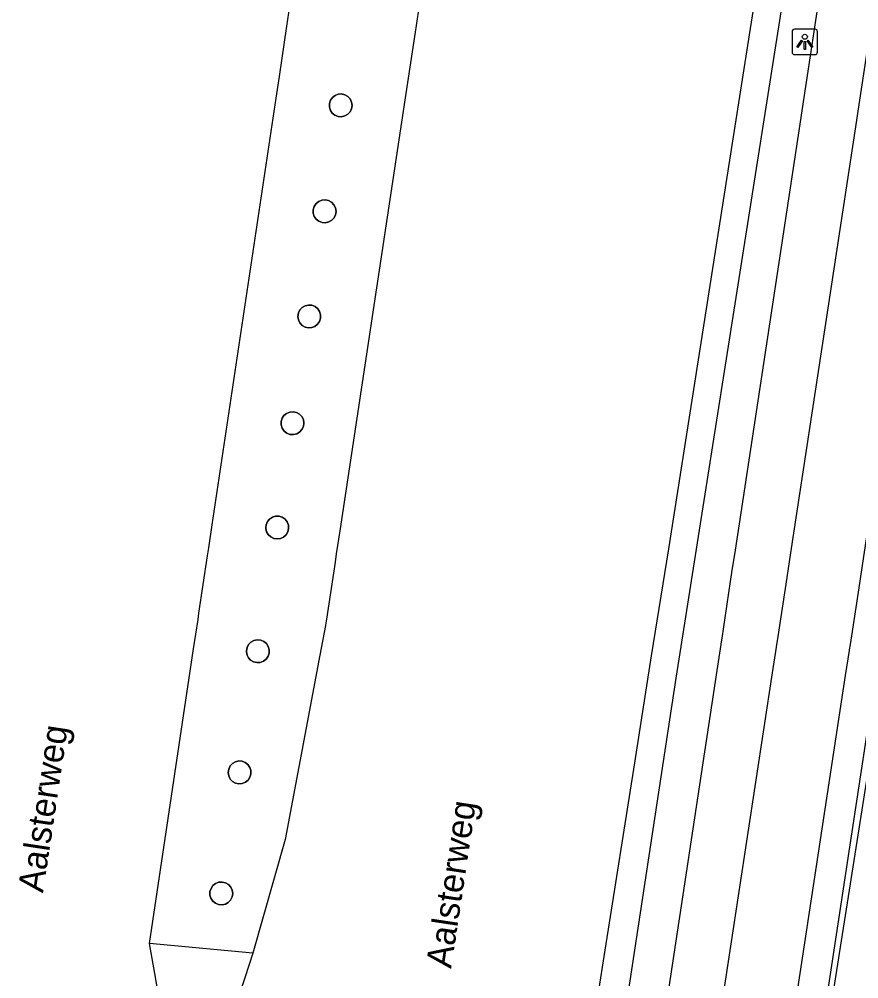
# Model space of a CAD drawing. Extents: x 161486 to 162249, y 379484 to 380829.
# Drawn here: x 161490.61 to 161523.59, y 379544.29 to 379582.01 of the extents above; entities that cross this region are included whole.
import ezdxf

# ---------------------------------------------------------------- set-up
doc = ezdxf.new("R2010")
doc.units = 0
for name, color, linetype in [('IMGEO_Berm_groen', 7, 'Continuous'), ('IMGEO_Berm_onverhard', 7, 'Continuous'), ('IMGEO_Fietspad_open', 7, 'Continuous'), ('IMGEO_Lichtpunt', 7, 'Continuous'), ('IMGEO_Openbare_ruimte_label', 7, 'Continuous'), ('IMGEO_Pijler', 7, 'Continuous'), ('IMGEO_Rijbaan_regionaal_gesloten', 7, 'Continuous'), ('IMGEO_Terreindeel_gesloten', 7, 'Continuous'), ('IMGEO_Verkeerseiland_open', 7, 'Continuous'), ('IMGEO_Voetpad_open', 7, 'Continuous')]:
    doc.layers.add(name, color=color, linetype=linetype)

msp = doc.modelspace()

# ---------------------------------------------------------------- linework, layer by layer
at = {"layer": 'IMGEO_Berm_groen'}
for points in [[(161516.417, 379556.106), (161526.18, 379618.14)], [(161527.294, 379617.58), (161527.259, 379617.352), (161527.039, 379615.902), (161525.083, 379603.014), (161524.95, 379602.133), (161524.942, 379602.083), (161524.556, 379599.541), (161524.518, 379599.289), (161524.48, 379599.039), (161524.465, 379598.94), (161524.312, 379597.933), (161521.822, 379581.524), (161521.704, 379580.745), (161521.403, 379578.761), (161521.27, 379577.888), (161518.729, 379561.143), (161518.595, 379560.258), (161518.543, 379559.914), (161518.204, 379557.678), (161518.171, 379557.462), (161518.167, 379557.439), (161518.011, 379556.409), (161516.057, 379543.535)], [(161514.521, 379543.608), (161516.417, 379556.106)]]:
    msp.add_lwpolyline(points, dxfattribs=at)
at = {"layer": 'IMGEO_Berm_onverhard'}
for points in [[(161503.402, 379579.044), (161503.517, 379578.976), (161503.608, 379578.878), (161503.665, 379578.757), (161503.685, 379578.624), (161503.665, 379578.492), (161503.606, 379578.372), (161503.515, 379578.274), (161503.399, 379578.207), (161503.269, 379578.177), (161503.135, 379578.187), (161503.011, 379578.236), (161502.906, 379578.319), (161502.83, 379578.429), (161502.79, 379578.557), (161502.79, 379578.691), (161502.819, 379578.798), (161502.832, 379578.825), (161502.908, 379578.935), (161503.013, 379579.018), (161503.138, 379579.065), (161503.272, 379579.074), (161503.402, 379579.044)], [(161502.877, 379574.815), (161502.97, 379574.718), (161503.029, 379574.598), (161503.052, 379574.459), (161503.032, 379574.327), (161502.974, 379574.206), (161502.883, 379574.108), (161502.767, 379574.041), (161502.637, 379574.01), (161502.504, 379574.02), (161502.379, 379574.068), (161502.274, 379574.151), (161502.198, 379574.261), (161502.157, 379574.388), (161502.156, 379574.522), (161502.194, 379574.65), (161502.269, 379574.762), (161502.372, 379574.846), (161502.496, 379574.897), (161502.63, 379574.908), (161502.76, 379574.88), (161502.877, 379574.815)], [(161502.231, 379570.716), (161502.335, 379570.631), (161502.409, 379570.52), (161502.448, 379570.392), (161502.446, 379570.258), (161502.406, 379570.13), (161502.33, 379570.02), (161502.225, 379569.937), (161502.1, 379569.889), (161501.967, 379569.88), (161501.836, 379569.91), (161501.721, 379569.977), (161501.63, 379570.075), (161501.572, 379570.196), (161501.552, 379570.328), (161501.574, 379570.468), (161501.634, 379570.587), (161501.726, 379570.684), (161501.843, 379570.749), (161501.974, 379570.777), (161502.107, 379570.766), (161502.231, 379570.716)], [(161501.709, 379566.392), (161501.769, 379566.273), (161501.791, 379566.133), (161501.771, 379566.001), (161501.713, 379565.88), (161501.622, 379565.782), (161501.507, 379565.715), (161501.376, 379565.685), (161501.243, 379565.694), (161501.118, 379565.742), (161501.013, 379565.825), (161500.937, 379565.935), (161500.897, 379566.063), (161500.895, 379566.196), (161500.934, 379566.325), (161501.008, 379566.436), (161501.112, 379566.52), (161501.236, 379566.571), (161501.369, 379566.582), (161501.5, 379566.554), (161501.617, 379566.489), (161501.709, 379566.392)], [(161501.05, 379562.359), (161501.132, 379562.254), (161501.18, 379562.129), (161501.189, 379561.995), (161501.158, 379561.865), (161501.091, 379561.749), (161500.992, 379561.659), (161500.871, 379561.602), (161500.739, 379561.582), (161500.607, 379561.603), (161500.486, 379561.661), (161500.388, 379561.752), (161500.322, 379561.868), (161500.292, 379561.998), (161500.291, 379562.039), (161500.303, 379562.139), (161500.354, 379562.263), (161500.439, 379562.366), (161500.551, 379562.44), (161500.679, 379562.478), (161500.813, 379562.476), (161500.94, 379562.435), (161501.05, 379562.359)], [(161500.392, 379557.359), (161500.429, 379557.23), (161500.427, 379557.096), (161500.385, 379556.969), (161500.307, 379556.86), (161500.201, 379556.779), (161500.076, 379556.732), (161499.942, 379556.724), (161499.812, 379556.756), (161499.697, 379556.824), (161499.619, 379556.912), (161499.563, 379557.01), (161499.534, 379557.141), (161499.533, 379557.185), (161499.557, 379557.317), (161499.618, 379557.436), (161499.712, 379557.531), (161499.829, 379557.595), (161499.96, 379557.622), (161500.093, 379557.608), (161500.217, 379557.557), (161500.32, 379557.471), (161500.392, 379557.359)], [(161499.709, 379552.477), (161499.71, 379552.343), (161499.672, 379552.215), (161499.598, 379552.103), (161499.494, 379552.019), (161499.37, 379551.968), (161499.237, 379551.957), (161499.106, 379551.985), (161498.989, 379552.05), (161498.897, 379552.147), (161498.837, 379552.267), (161498.815, 379552.406), (161498.835, 379552.538), (161498.893, 379552.659), (161498.983, 379552.757), (161499.099, 379552.824), (161499.229, 379552.855), (161499.363, 379552.845), (161499.488, 379552.797), (161499.593, 379552.714), (161499.669, 379552.604), (161499.709, 379552.477)], [(161498.995, 379547.649), (161498.973, 379547.51), (161498.913, 379547.39), (161498.821, 379547.294), (161498.704, 379547.228), (161498.573, 379547.2), (161498.44, 379547.212), (161498.316, 379547.262), (161498.212, 379547.347), (161498.138, 379547.458), (161498.1, 379547.586), (161498.101, 379547.72), (161498.141, 379547.847), (161498.217, 379547.957), (161498.322, 379548.04), (161498.447, 379548.088), (161498.581, 379548.098), (161498.711, 379548.068), (161498.827, 379548), (161498.917, 379547.902), (161498.975, 379547.782), (161498.995, 379547.649)]]:
    msp.add_lwpolyline(points, dxfattribs=at)
at = {"layer": 'IMGEO_Fietspad_open'}
for points in [[(161529.477, 379617.475), (161529.443, 379617.251), (161529.222, 379615.794), (161527.27, 379602.91), (161527.136, 379602.026), (161527.129, 379601.975), (161526.744, 379599.436), (161526.705, 379599.18), (161526.668, 379598.93), (161526.652, 379598.831), (161526.5, 379597.828), (161524.015, 379581.417), (161523.897, 379580.639), (161523.596, 379578.655), (161523.463, 379577.78), (161520.907, 379561.037), (161520.772, 379560.153), (161520.72, 379559.808), (161520.379, 379557.573), (161520.346, 379557.359), (161520.342, 379557.335), (161520.188, 379556.324), (161518.221, 379543.432)], [(161521.107, 379543.294), (161523.074, 379556.211), (161523.224, 379557.197), (161523.228, 379557.223), (161523.26, 379557.434), (161523.6, 379559.667), (161523.653, 379560.015), (161523.788, 379560.897), (161526.337, 379577.638), (161526.471, 379578.515), (161526.773, 379580.5), (161526.891, 379581.277), (161529.388, 379597.69), (161529.539, 379598.688), (161529.554, 379598.787), (161529.588, 379599.006), (161529.593, 379599.038), (161529.632, 379599.297), (161530.018, 379601.833), (161530.026, 379601.884), (161530.161, 379602.772), (161532.12, 379615.65), (161532.343, 379617.118), (161532.376, 379617.336)]]:
    msp.add_lwpolyline(points, dxfattribs=at)
at = {"layer": 'IMGEO_Lichtpunt'}
for p, q in [((161520.971, 379581.522), (161520.971, 379580.715)), ((161520.971, 379581.522), (161520.971, 379580.715)), ((161521.873, 379581.617), (161521.065, 379581.617)), ((161521.873, 379581.617), (161521.065, 379581.617)), ((161521.967, 379580.715), (161521.967, 379581.522)), ((161521.967, 379580.715), (161521.967, 379581.522)), ((161521.065, 379580.621), (161521.873, 379580.621)), ((161521.065, 379580.621), (161521.873, 379580.621))]:
    msp.add_line(p, q, dxfattribs=at)
for points in [[(161521.345, 379581.186), (161521.384, 379581.158), (161521.196, 379580.896), (161521.158, 379580.923), (161521.345, 379581.186)], [(161521.447, 379581.138), (161521.494, 379581.138), (161521.494, 379580.816), (161521.447, 379580.816), (161521.447, 379581.138)], [(161521.557, 379581.158), (161521.595, 379581.185), (161521.782, 379580.923), (161521.743, 379580.895), (161521.557, 379581.158)]]:
    msp.add_lwpolyline(points, dxfattribs=at)
msp.add_circle((161521.47, 379581.32), 0.0994, dxfattribs=at)
for centre, start, end in [((161521.065, 379581.522), 90, 180), ((161521.065, 379581.522), 90, 180), ((161521.873, 379581.522), 0, 90), ((161521.873, 379581.522), 0, 90), ((161521.065, 379580.715), 180, 270), ((161521.065, 379580.715), 180, 270), ((161521.873, 379580.715), 270, 0), ((161521.873, 379580.715), 270, 360)]:
    msp.add_arc(centre, 0.0946, start, end, dxfattribs=at)
at = {"layer": 'IMGEO_Pijler'}
for points in [[(161503.685, 379578.624), (161503.665, 379578.757), (161503.608, 379578.878), (161503.517, 379578.976), (161503.402, 379579.044), (161503.272, 379579.074), (161503.138, 379579.065), (161503.013, 379579.018), (161502.908, 379578.935), (161502.832, 379578.825), (161502.819, 379578.798), (161502.79, 379578.691), (161502.79, 379578.557), (161502.83, 379578.429), (161502.906, 379578.319), (161503.011, 379578.236), (161503.135, 379578.187), (161503.269, 379578.177), (161503.399, 379578.207), (161503.515, 379578.274), (161503.606, 379578.372), (161503.665, 379578.492)], [(161502.97, 379574.718), (161502.877, 379574.815), (161502.76, 379574.88), (161502.63, 379574.908), (161502.496, 379574.897), (161502.372, 379574.846), (161502.269, 379574.762), (161502.194, 379574.65), (161502.156, 379574.522), (161502.157, 379574.388), (161502.198, 379574.261), (161502.274, 379574.151), (161502.379, 379574.068), (161502.504, 379574.02), (161502.637, 379574.01), (161502.767, 379574.041), (161502.883, 379574.108), (161502.974, 379574.206), (161503.032, 379574.327), (161503.052, 379574.459), (161503.029, 379574.598)], [(161502.448, 379570.392), (161502.409, 379570.52), (161502.335, 379570.631), (161502.231, 379570.716), (161502.107, 379570.766), (161501.974, 379570.777), (161501.843, 379570.749), (161501.726, 379570.684), (161501.634, 379570.587), (161501.574, 379570.468), (161501.552, 379570.328), (161501.572, 379570.196), (161501.63, 379570.075), (161501.721, 379569.977), (161501.836, 379569.91), (161501.967, 379569.88), (161502.1, 379569.889), (161502.225, 379569.937), (161502.33, 379570.02), (161502.406, 379570.13), (161502.446, 379570.258)], [(161501.769, 379566.273), (161501.709, 379566.392), (161501.617, 379566.489), (161501.5, 379566.554), (161501.369, 379566.582), (161501.236, 379566.571), (161501.112, 379566.52), (161501.008, 379566.436), (161500.934, 379566.325), (161500.895, 379566.196), (161500.897, 379566.063), (161500.937, 379565.935), (161501.013, 379565.825), (161501.118, 379565.742), (161501.243, 379565.694), (161501.376, 379565.685), (161501.507, 379565.715), (161501.622, 379565.782), (161501.713, 379565.88), (161501.771, 379566.001), (161501.791, 379566.133)], [(161501.18, 379562.129), (161501.132, 379562.254), (161501.05, 379562.359), (161500.94, 379562.435), (161500.813, 379562.476), (161500.679, 379562.478), (161500.551, 379562.44), (161500.439, 379562.366), (161500.354, 379562.263), (161500.303, 379562.139), (161500.291, 379562.039), (161500.292, 379561.998), (161500.322, 379561.868), (161500.388, 379561.752), (161500.486, 379561.661), (161500.607, 379561.603), (161500.739, 379561.582), (161500.871, 379561.602), (161500.992, 379561.659), (161501.091, 379561.749), (161501.158, 379561.865), (161501.189, 379561.995)], [(161500.429, 379557.23), (161500.392, 379557.359), (161500.32, 379557.471), (161500.217, 379557.557), (161500.093, 379557.608), (161499.96, 379557.622), (161499.829, 379557.595), (161499.712, 379557.531), (161499.618, 379557.436), (161499.557, 379557.317), (161499.533, 379557.185), (161499.534, 379557.141), (161499.563, 379557.01), (161499.619, 379556.912), (161499.697, 379556.824), (161499.812, 379556.756), (161499.942, 379556.724), (161500.076, 379556.732), (161500.201, 379556.779), (161500.307, 379556.86), (161500.385, 379556.969), (161500.427, 379557.096)], [(161499.709, 379552.477), (161499.669, 379552.604), (161499.593, 379552.714), (161499.488, 379552.797), (161499.363, 379552.845), (161499.229, 379552.855), (161499.099, 379552.824), (161498.983, 379552.757), (161498.893, 379552.659), (161498.835, 379552.538), (161498.815, 379552.406), (161498.837, 379552.267), (161498.897, 379552.147), (161498.989, 379552.05), (161499.106, 379551.985), (161499.237, 379551.957), (161499.37, 379551.968), (161499.494, 379552.019), (161499.598, 379552.103), (161499.672, 379552.215), (161499.71, 379552.343)], [(161498.975, 379547.782), (161498.917, 379547.902), (161498.827, 379548), (161498.711, 379548.068), (161498.581, 379548.098), (161498.447, 379548.088), (161498.322, 379548.04), (161498.217, 379547.957), (161498.141, 379547.847), (161498.101, 379547.72), (161498.1, 379547.586), (161498.138, 379547.458), (161498.212, 379547.347), (161498.316, 379547.262), (161498.44, 379547.212), (161498.573, 379547.2), (161498.704, 379547.228), (161498.821, 379547.294), (161498.913, 379547.39), (161498.973, 379547.51), (161498.995, 379547.649)]]:
    msp.add_lwpolyline(points, close=True, dxfattribs=at)
at = {"layer": 'IMGEO_Rijbaan_regionaal_gesloten'}
for points in [[(161513.354, 379543.664), (161513.63, 379545.417), (161514.79, 379552.78), (161515.453, 379556.988), (161516.133, 379561.19), (161519.339, 379581.651), (161522.723, 379603.127), (161524.864, 379616.082), (161525.01, 379617.635), (161525.102, 379618.199)], [(161495.724, 379545.685), (161497.459, 379557.264), (161497.632, 379558.421), (161497.669, 379558.667), (161498.006, 379560.919), (161498.053, 379561.232), (161498.19, 379562.141), (161500.701, 379578.903), (161500.83, 379579.763), (161501.126, 379581.741), (161501.244, 379582.528), (161503.7, 379598.919), (161503.856, 379599.964), (161503.871, 379600.063), (161503.901, 379600.263), (161503.908, 379600.307), (161503.942, 379600.535), (161504.326, 379603.098), (161504.333, 379603.144), (161504.461, 379603.999), (161506.336, 379616.511)], [(161511.348, 379615.831), (161509.524, 379603.758), (161509.394, 379602.896), (161509.387, 379602.85), (161509, 379600.291), (161508.965, 379600.057), (161508.959, 379600.016), (161508.928, 379599.812), (161508.913, 379599.713), (161508.756, 379598.677), (161506.279, 379582.283), (161506.161, 379581.497), (161505.862, 379579.518), (161505.731, 379578.655), (161503.2, 379561.897), (161503.064, 379561.002), (161503.015, 379560.674), (161502.675, 379558.426), (161502.641, 379558.199), (161502.638, 379558.181), (161502.419, 379557.018), (161501.057, 379549.772), (161499.787, 379545.305)], [(161497.459, 379557.264), (161497.632, 379558.421), (161497.669, 379558.667), (161498.006, 379560.919), (161498.053, 379561.232), (161498.19, 379562.141), (161500.701, 379578.903), (161500.83, 379579.763), (161501.126, 379581.741), (161501.244, 379582.528)], [(161506.279, 379582.283), (161506.161, 379581.497), (161505.862, 379579.518), (161505.731, 379578.655), (161503.2, 379561.897), (161503.064, 379561.002), (161503.015, 379560.674), (161502.675, 379558.426), (161502.641, 379558.199), (161502.638, 379558.181), (161502.419, 379557.018), (161501.057, 379549.772), (161499.787, 379545.305), (161499.467, 379544.328), (161498.739, 379542.103)], [(161497.156, 379540.427), (161496.557, 379540.903), (161496.379, 379541.925), (161496.328, 379542.221), (161495.931, 379544.496), (161495.724, 379545.685), (161497.459, 379557.264)], [(161497.156, 379540.427), (161496.557, 379540.903), (161496.379, 379541.925), (161496.328, 379542.221), (161495.931, 379544.496), (161495.724, 379545.685)], [(161499.787, 379545.305), (161499.467, 379544.328), (161498.739, 379542.103), (161498.645, 379541.814), (161498.412, 379541.104)]]:
    msp.add_lwpolyline(points, dxfattribs=at)
at = {"layer": 'IMGEO_Terreindeel_gesloten'}
msp.add_lwpolyline([(161533.61, 379617.571), (161533.916, 379617.524), (161531.211, 379599.82), (161528.651, 379582.901), (161525.389, 379561.578), (161522.095, 379540.718)], dxfattribs=at)
at = {"layer": 'IMGEO_Verkeerseiland_open'}
msp.add_lwpolyline([(161499.787, 379545.305), (161495.724, 379545.685)], dxfattribs=at)
at = {"layer": 'IMGEO_Voetpad_open'}
msp.add_lwpolyline([(161533.565, 379617.278), (161530.87, 379599.866), (161528.339, 379583.017), (161525.07, 379561.614), (161521.903, 379540.764)], dxfattribs=at)

# ---------------------------------------------------------------- texts
at = {"layer": 'IMGEO_Openbare_ruimte_label'}
for p in [(161491.538, 379547.651), (161507.573, 379544.677)]:
    msp.add_text('Aalsterweg', height=1, rotation=81.4324, dxfattribs=at).set_placement(p)

doc.saveas('drawing.dxf')
